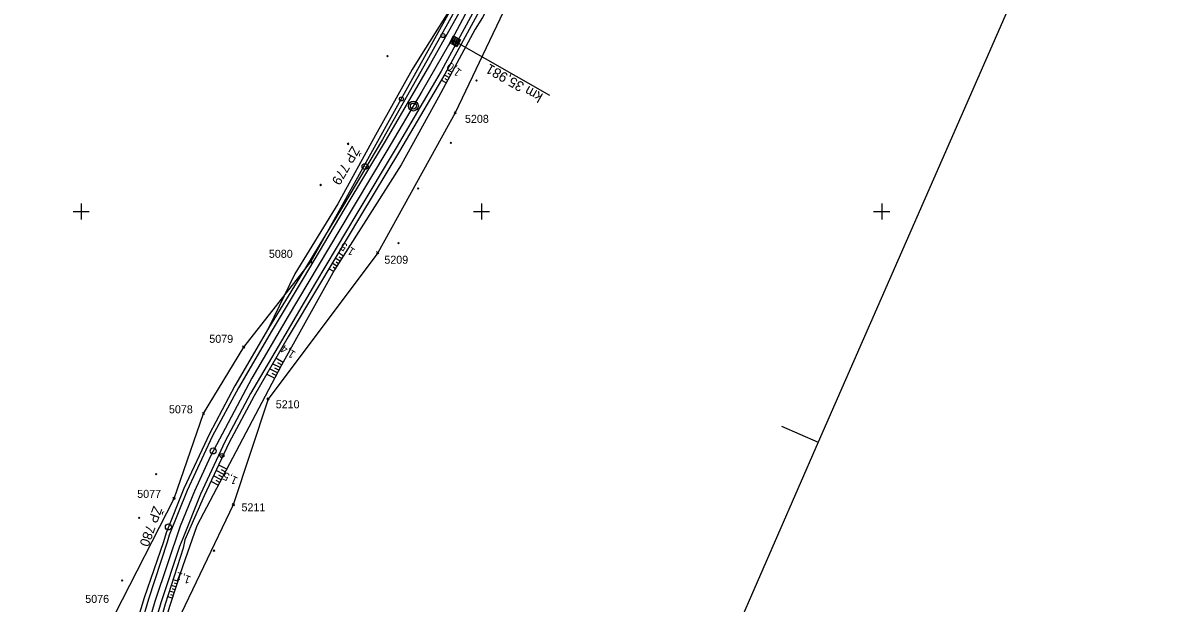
# Model space of a CAD drawing. Extents: x -806856 to -806332, y -1151642 to -1150946.
# Drawn here: x -806614.6 to -806331.6, y -1151297.9 to -1151152.8 of the extents above; entities that cross this region are included whole.
import ezdxf

# ---------------------------------------------------------------- set-up
doc = ezdxf.new("R2010")
doc.units = 0
for name, color, linetype in [('0381KM032-037P - Vrstva 1', 7, 'Continuous'), ('0381KM032-037P - Vrstva 27', 7, 'Continuous'), ('0381KM032-037P - Vrstva 3', 7, 'Continuous'), ('0381KM032-037P - Vrstva 4', 7, 'Continuous'), ('0381KM032-037P - Vrstva 48', 7, 'Continuous'), ('0381KM032-037P - Vrstva 49', 7, 'Continuous'), ('0381KM032-037P - Vrstva 7', 7, 'Continuous'), ('formát', 7, 'Continuous'), ('krizky_1000 - Vrstva 1', 7, 'Continuous'), ('szdc - hran DP', 7, 'Continuous'), ('szdc - szdc_cislo', 7, 'Continuous'), ('szdc - szdc_krizek', 7, 'Continuous'), ('vyt_sit - ohrožené', 7, 'Continuous'), ('vyt_sit - stávající', 7, 'Continuous')]:
    doc.layers.add(name, color=color, linetype=linetype)

msp = doc.modelspace()

# ---------------------------------------------------------------- linework, layer by layer
at = {"layer": '0381KM032-037P - Vrstva 1'}
for points in [[(-806459.11, -1151042.15), (-806463.27, -1151055.58), (-806467.76, -1151068.75), (-806472.65, -1151081.99), (-806477.96, -1151095.43), (-806483.66, -1151108.91), (-806489.46, -1151121.74), (-806491.74, -1151126.53), (-806497.91, -1151139.08), (-806504.69, -1151152.02), (-806507.41, -1151157), (-806508.24, -1151158.47)], [(-806508.24, -1151158.47), (-806514.85, -1151170.04), (-806523.65, -1151184.88)], [(-806523.65, -1151184.88), (-806535.6, -1151204.92), (-806548.25, -1151226.13)], [(-806548.25, -1151226.13), (-806557.37, -1151241.69), (-806567.71, -1151261.13)], [(-806567.71, -1151261.13), (-806571.7, -1151269.85), (-806575.25, -1151278.64)], [(-806575.26, -1151278.66), (-806581.61, -1151297.45), (-806587.32, -1151317.2)]]:
    msp.add_lwpolyline(points, dxfattribs=at)
at = {"layer": '0381KM032-037P - Vrstva 27'}
msp.add_line((-806509.65, -1151156.05), (-806509.55, -1151156.05), dxfattribs=at)
msp.add_circle((-806509.6, -1151156.05), 0.5, dxfattribs=at)
at = {"layer": '0381KM032-037P - Vrstva 3'}
for p, q in [((-806507.53, -1151158.07), (-806507.7, -1151157.51)), ((-806507.07, -1151158.32), (-806507.44, -1151157.05)), ((-806507.41, -1151157), (-806483.02, -1151170.91)), ((-806506.6, -1151158.58), (-806507.19, -1151156.58)), ((-806506.14, -1151158.83), (-806506.93, -1151156.12)), ((-806505.88, -1151158.37), (-806506.47, -1151156.37)), ((-806505.63, -1151157.9), (-806506, -1151156.63)), ((-806505.37, -1151157.44), (-806505.54, -1151156.88))]:
    msp.add_line(p, q, dxfattribs=at)
msp.add_lwpolyline([(-806507.89, -1151157.87), (-806506.93, -1151156.12), (-806505.18, -1151157.08), (-806506.14, -1151158.83)], close=True, dxfattribs=at)
at = {"layer": '0381KM032-037P - Vrstva 4'}
for points in [[(-806449.56, -1151013.68), (-806449.62, -1151013.88), (-806452.81, -1151025.46), (-806457.3, -1151041.13), (-806462.78, -1151058.55), (-806470.34, -1151080.36), (-806477.94, -1151099.38), (-806485.55, -1151116.61), (-806493.04, -1151132.58), (-806500.67, -1151147.66), (-806510.08, -1151164.94), (-806521.27, -1151184.09), (-806531.11, -1151200.55)], [(-806448.21, -1151014.27), (-806448.22, -1151014.33), (-806451.54, -1151025.93), (-806456.14, -1151041.58), (-806461.64, -1151059.21), (-806469.17, -1151081.08), (-806476.72, -1151099.82), (-806484.37, -1151117.46), (-806491.94, -1151132.93), (-806500.08, -1151149.04), (-806509.16, -1151165.69), (-806520.46, -1151184.9), (-806530.22, -1151201.05)], [(-806453.41, -1151012), (-806457.09, -1151024.8), (-806461.35, -1151040.24), (-806466.6, -1151057.45), (-806474.53, -1151080.31), (-806481.65, -1151097.72), (-806488.93, -1151114.87), (-806496.54, -1151130.59), (-806504.49, -1151145.86), (-806513.59, -1151162.34)], [(-806452.41, -1151012.43), (-806452.61, -1151013.14), (-806455.7, -1151025.15), (-806460.24, -1151040.55), (-806465.79, -1151057.73), (-806473.74, -1151080.66), (-806480.83, -1151098.02), (-806488.21, -1151115.16), (-806495.76, -1151130.97), (-806503.39, -1151146.39), (-806512.71, -1151163.05)], [(-806513.59, -1151162.34), (-806524.74, -1151181.99), (-806534.73, -1151198.81)], [(-806512.71, -1151163.05), (-806524.03, -1151182.45), (-806534.14, -1151199.19)], [(-806534.73, -1151198.81), (-806545.37, -1151216.39), (-806553.18, -1151229.13), (-806561.58, -1151243.53), (-806567.96, -1151255.6), (-806574.3, -1151269.24), (-806578.76, -1151280.27), (-806579.4, -1151282.54), (-806584.22, -1151296.56), (-806589.48, -1151313.82), (-806594.95, -1151333.92), (-806600.1, -1151352.67), (-806608.81, -1151384.22), (-806613.08, -1151400.58)], [(-806534.14, -1151199.19), (-806544.55, -1151216.75), (-806552.31, -1151229.7), (-806560.71, -1151244.03), (-806567.24, -1151256.24), (-806573.52, -1151269.73), (-806577.97, -1151280.92), (-806578.5, -1151282.67), (-806583.15, -1151296.86), (-806588.26, -1151314.07), (-806594.08, -1151334.22), (-806599.38, -1151352.89), (-806608.02, -1151384.26), (-806612.6, -1151400.79)], [(-806531.11, -1151200.55), (-806541.48, -1151217.8), (-806549.08, -1151230.92), (-806557.69, -1151245.47), (-806564.05, -1151257.36), (-806570.21, -1151270.63), (-806574.62, -1151281.75), (-806575.45, -1151283.67), (-806580.1, -1151297.77), (-806585.12, -1151314.97), (-806590.56, -1151334.63), (-806595.8, -1151353.37), (-806604.61, -1151384.9), (-806609.41, -1151402.19)], [(-806530.22, -1151201.05), (-806540.66, -1151218.65), (-806548.31, -1151231.35), (-806556.78, -1151246.08), (-806563.07, -1151257.89), (-806569.22, -1151271.02), (-806574.1, -1151282.08), (-806574.48, -1151284.1), (-806578.97, -1151298.16), (-806583.83, -1151315.38), (-806589.34, -1151334.88), (-806594.45, -1151353.63), (-806603.42, -1151385.04), (-806608.69, -1151402.5)]]:
    msp.add_lwpolyline(points, dxfattribs=at)
at = {"layer": '0381KM032-037P - Vrstva 48'}
for p, q in [((-806508.1, -1151166.54), (-806509.29, -1151165.9)), ((-806508.45, -1151167.2), (-806509.06, -1151166.88)), ((-806507.39, -1151165.22), (-806508.56, -1151164.59)), ((-806507.74, -1151165.88), (-806508.33, -1151165.56)), ((-806508.81, -1151167.86), (-806510.05, -1151167.2)), ((-806535.27, -1151212.43), (-806536.5, -1151211.65)), ((-806534.47, -1151211.16), (-806535.73, -1151210.35)), ((-806534.87, -1151211.79), (-806535.49, -1151211.4)), ((-806536.85, -1151214.97), (-806538.08, -1151214.31)), ((-806536.08, -1151213.69), (-806537.27, -1151212.94)), ((-806536.48, -1151214.33), (-806537.06, -1151213.95)), ((-806535.67, -1151213.06), (-806536.28, -1151212.68)), ((-806549.55, -1151237.71), (-806551.38, -1151236.68)), ((-806549.91, -1151238.36), (-806550.83, -1151237.85)), ((-806551.66, -1151241.68), (-806553.65, -1151240.63)), ((-806550.96, -1151240.35), (-806552.9, -1151239.33)), ((-806551.31, -1151241.01), (-806552.29, -1151240.5)), ((-806550.26, -1151239.02), (-806552.15, -1151238.03)), ((-806550.61, -1151239.69), (-806551.57, -1151239.18)), ((-806563.63, -1151264.4), (-806565.62, -1151263.35)), ((-806565.02, -1151267.05), (-806566.9, -1151266.07)), ((-806564.33, -1151265.73), (-806566.26, -1151264.71)), ((-806564.67, -1151266.39), (-806565.63, -1151265.89)), ((-806563.97, -1151265.06), (-806564.96, -1151264.54)), ((-806565.72, -1151268.38), (-806567.54, -1151267.43)), ((-806565.37, -1151267.72), (-806566.3, -1151267.23)), ((-806576.33, -1151293.8), (-806577.46, -1151293.43)), ((-806576.56, -1151294.51), (-806577.15, -1151294.32)), ((-806575.86, -1151292.37), (-806577, -1151292)), ((-806576.1, -1151293.08), (-806576.71, -1151292.89)), ((-806577.26, -1151296.65), (-806578.37, -1151296.29)), ((-806576.79, -1151295.22), (-806577.92, -1151294.86)), ((-806577.02, -1151295.94), (-806577.6, -1151295.75))]:
    msp.add_line(p, q, dxfattribs=at)
at = {"layer": '0381KM032-037P - Vrstva 49'}
for p, q in [((-806523.3, -1151161.03), (-806523.66, -1151161.38)), ((-806523.66, -1151161.03), (-806523.3, -1151161.38)), ((-806501.03, -1151167.07), (-806501.39, -1151167.43)), ((-806501.39, -1151167.08), (-806501.03, -1151167.43)), ((-806533.51, -1151182.94), (-806533.15, -1151183.29)), ((-806533.15, -1151182.94), (-806533.5, -1151183.29)), ((-806507.48, -1151182.67), (-806507.84, -1151183.02)), ((-806507.84, -1151182.67), (-806507.48, -1151183.02)), ((-806540.04, -1151193.21), (-806540.39, -1151193.57)), ((-806540.39, -1151193.21), (-806540.03, -1151193.57)), ((-806515.61, -1151194.06), (-806515.96, -1151194.41)), ((-806515.96, -1151194.06), (-806515.61, -1151194.41)), ((-806520.55, -1151207.75), (-806520.9, -1151208.11)), ((-806520.9, -1151207.76), (-806520.54, -1151208.11)), ((-806581.43, -1151265.45), (-806581.07, -1151265.8)), ((-806581.07, -1151265.45), (-806581.42, -1151265.81)), ((-806585.29, -1151276.36), (-806585.64, -1151276.72)), ((-806585.64, -1151276.36), (-806585.29, -1151276.72)), ((-806566.67, -1151284.56), (-806567.02, -1151284.92)), ((-806567.02, -1151284.56), (-806566.66, -1151284.92)), ((-806589.55, -1151292.05), (-806589.91, -1151292.41)), ((-806589.91, -1151292.05), (-806589.55, -1151292.41))]:
    msp.add_line(p, q, dxfattribs=at)
for points in [[(-806448.2, -1151014.28), (-806448.22, -1151014.33), (-806451.54, -1151025.93), (-806456.14, -1151041.58), (-806461.64, -1151059.21), (-806469.17, -1151081.08), (-806476.72, -1151099.82), (-806484.37, -1151117.46), (-806491.94, -1151132.93), (-806500.08, -1151149.04), (-806509.16, -1151165.69), (-806520.46, -1151184.9), (-806530.22, -1151201.05)], [(-806446.83, -1151014.88), (-806447.16, -1151016), (-806450, -1151026.43), (-806453.97, -1151042.26), (-806459.11, -1151060.35), (-806468.36, -1151084.26), (-806475.1, -1151100.8), (-806483.46, -1151117.96), (-806490.37, -1151133.75), (-806499.76, -1151151.57), (-806501.59, -1151154.48), (-806510.73, -1151171.42), (-806520.01, -1151188.39)], [(-806496.54, -1151130.59), (-806505.32, -1151145.34), (-806515.42, -1151161.45), (-806517.29, -1151164.53), (-806526.47, -1151180.94), (-806535.85, -1151198.12)], [(-806520.01, -1151188.39), (-806536.66, -1151214.61), (-806549.93, -1151238.4), (-806571.09, -1151278.57), (-806574.7, -1151288.79), (-806577.92, -1151298.67), (-806582.99, -1151315.77), (-806588.39, -1151335.12), (-806593.7, -1151353.88), (-806600.16, -1151386.57)], [(-806535.85, -1151198.12), (-806546.61, -1151215.57), (-806553.18, -1151229.13), (-806561.58, -1151243.53), (-806567.96, -1151255.6), (-806574.3, -1151269.24), (-806578.76, -1151280.27), (-806579.4, -1151282.54), (-806584.22, -1151296.56), (-806589.48, -1151313.82), (-806594.95, -1151333.92), (-806600.1, -1151352.67), (-806608.81, -1151384.22), (-806614.6, -1151399.91)], [(-806530.22, -1151201.05), (-806540.66, -1151218.65), (-806548.31, -1151231.35), (-806556.78, -1151246.08), (-806563.07, -1151257.89), (-806569.22, -1151271.02), (-806574.1, -1151282.08)], [(-806574.1, -1151282.08), (-806574.48, -1151284.1), (-806578.97, -1151298.16), (-806583.83, -1151315.38), (-806589.34, -1151334.88), (-806594.45, -1151353.63), (-806603.42, -1151385.04), (-806608.48, -1151402.59)]]:
    msp.add_lwpolyline(points, dxfattribs=at)
at = {"layer": '0381KM032-037P - Vrstva 7'}
for p, q in [((-806520.04, -1151171.89), (-806519.94, -1151171.89)), ((-806564.89, -1151260.99), (-806564.79, -1151260.99))]:
    msp.add_line(p, q, dxfattribs=at)
for centre, radius in [((-806519.99, -1151171.89), 0.5), ((-806517, -1151173.66), 1.25), ((-806517, -1151173.66), 0.752), ((-806567.02, -1151259.83), 0.75), ((-806564.84, -1151260.99), 0.5)]:
    msp.add_circle(centre, radius, dxfattribs=at)
at = {"layer": 'formát'}
for p, q in [((-806331.63, -1151065.3), (-806415.83, -1151257.68)), ((-806424.99, -1151253.67), (-806415.83, -1151257.68)), ((-806424.99, -1151253.67), (-806415.83, -1151257.68)), ((-806415.83, -1151257.68), (-806500.03, -1151450.06))]:
    msp.add_line(p, q, dxfattribs=at)
at = {"layer": 'krizky_1000 - Vrstva 1'}
for points in [[(-806600, -1151198), (-806600, -1151202)], [(-806500, -1151198), (-806500, -1151202)], [(-806400, -1151198), (-806400, -1151202)], [(-806602, -1151200), (-806598, -1151200)], [(-806502, -1151200), (-806498, -1151200)], [(-806402, -1151200), (-806398, -1151200)]]:
    msp.add_lwpolyline(points, dxfattribs=at)
at = {"layer": 'szdc - hran DP'}
for p, q in [((-806485.36, -1151130.76), (-806506.53, -1151175.36)), ((-806542.64, -1151212.58), (-806506.25, -1151146.99)), ((-806506.53, -1151175.36), (-806525.91, -1151210.3)), ((-806525.91, -1151210.3), (-806553.28, -1151246.87)), ((-806559.38, -1151233.91), (-806542.64, -1151212.58)), ((-806569.42, -1151250.48), (-806559.38, -1151233.91)), ((-806553.28, -1151246.87), (-806561.98, -1151273.31)), ((-806576.79, -1151271.69), (-806569.42, -1151250.48)), ((-806591.51, -1151300.57), (-806576.79, -1151271.69)), ((-806561.98, -1151273.31), (-806579.39, -1151309.52))]:
    msp.add_line(p, q, dxfattribs=at)
at = {"layer": 'szdc - szdc_krizek'}
for p, q in [((-806506.27, -1151175.62), (-806506.8, -1151175.09)), ((-806506.8, -1151175.62), (-806506.27, -1151175.09)), ((-806542.38, -1151212.84), (-806542.91, -1151212.31)), ((-806542.91, -1151212.84), (-806542.38, -1151212.31)), ((-806525.65, -1151210.56), (-806526.18, -1151210.03)), ((-806526.18, -1151210.56), (-806525.65, -1151210.03)), ((-806559.11, -1151234.18), (-806559.65, -1151233.65)), ((-806559.65, -1151234.18), (-806559.11, -1151233.65)), ((-806553.02, -1151247.14), (-806553.55, -1151246.6)), ((-806553.55, -1151247.14), (-806553.02, -1151246.6)), ((-806569.16, -1151250.75), (-806569.69, -1151250.22)), ((-806569.69, -1151250.75), (-806569.16, -1151250.22)), ((-806576.53, -1151271.96), (-806577.06, -1151271.43)), ((-806577.06, -1151271.96), (-806576.53, -1151271.43)), ((-806561.71, -1151273.57), (-806562.25, -1151273.04)), ((-806562.25, -1151273.57), (-806561.71, -1151273.04))]:
    msp.add_line(p, q, dxfattribs=at)
at = {"layer": 'vyt_sit - ohrožené'}
msp.add_line((-806529.11, -1151188.76), (-806529.01, -1151188.76), dxfattribs=at)
msp.add_circle((-806529.06, -1151188.76), 0.756, dxfattribs=at)
at = {"layer": 'vyt_sit - stávající'}
msp.add_line((-806578.22, -1151278.81), (-806578.12, -1151278.81), dxfattribs=at)
msp.add_circle((-806578.18, -1151278.81), 0.756, dxfattribs=at)

# ---------------------------------------------------------------- texts
at = {"layer": '0381KM032-037P - Vrstva 3'}
msp.add_text('km 35,981', height=2.5, rotation=150.2693, dxfattribs=at).set_placement((-806484.41, -1151170.73))
at = {"layer": '0381KM032-037P - Vrstva 48'}
for s, rotation, p in [('1,0', 142.0922, (-806504.79, -1151164.89)), ('1,5', 147.9162, (-806531.38, -1151209.56)), ('1,4', 147.0433, (-806546.24, -1151235.23)), ('1,5', 154.8905, (-806560.68, -1151266.6)), ('1,1', 160.7839, (-806572.42, -1151291.27))]:
    msp.add_text(s, height=2, rotation=rotation, dxfattribs=at).set_placement(p)
at = {"layer": 'szdc - szdc_cislo'}
for s, p in [('5208', (-806504.1, -1151177.86)), ('5080', (-806553.09, -1151211.58)), ('5209', (-806524.24, -1151213.06)), ('5079', (-806567.97, -1151232.82)), ('5078', (-806578.05, -1151250.43)), ('5210', (-806551.37, -1151249.18)), ('5077', (-806585.98, -1151271.56)), ('5211', (-806559.93, -1151274.92)), ('5076', (-806598.96, -1151297.8))]:
    msp.add_text(s, height=2, dxfattribs=at).set_placement(p)
at = {"layer": 'vyt_sit - ohrožené'}
msp.add_text('ŽP 779', height=2.4, rotation=240, dxfattribs=at).set_placement((-806532.3, -1151183.48))
at = {"layer": 'vyt_sit - stávající'}
msp.add_text('ŽP 780', height=2.4, rotation=250, dxfattribs=at).set_placement((-806581.91, -1151273.42))

doc.saveas('drawing.dxf')
